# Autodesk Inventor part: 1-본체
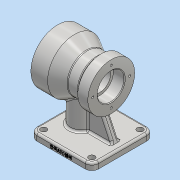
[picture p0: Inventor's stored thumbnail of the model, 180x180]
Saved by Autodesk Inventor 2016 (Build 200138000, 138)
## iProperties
Created: 2019-01
Part Number: 1-본체
Material: 알루미늄 6061
Document SubType Name: Modeling
Designer: Administrator
Density: 2.7 g/cm^3
Appearance: 알루미늄 - 평지
Mass: 904.622 g
Surface Area: 607.619 cm^2
Volume: 335.045 cm^3
Author: Administrator
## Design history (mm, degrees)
sketch "스케치2"
  geometry: L1 (0, 0)-(0, 40); L2 (0, 40)-(-25, 40); L3 (-25, 40)-(-44.053, 29); L4 (-44.053, 29)-(-59.965, 29); L5 (-59.965, 29)-(-65, 35); L6 (-65, 35)-(-80, 35); L7 (-80, 35)-(-80, 0); L8 (-80, 0)-(0, 0); L9 (0, 26)-(-20, 26); L10 (-20, 26)-(-20, 0); L11 (-80, 0)-(-63, 0); L12 (-63, 0)-(-63, 20); L13 (-63, 20)-(-80, 20); L14 (-80, 20)-(-80, 0); L15 (-20, 16)-(-63, 16); 1 further point
  constraints: 30 end point, 6 perpendicular, 4 parallel, 4 point on line, 2 horizontal, 1 coincident, 1 vertical
  dimensions: "d0" = 70 diameter of L6 L8; "d1" = 58 diameter of L4 L8; "d2" = 80 diameter of L2 L8; "d3" = 25 distance of L1.end L2.end; "d4" = 80 distance between parallel lines of L7 L1; "d5" = 15 distance of L5.end L6.end; "d6" = 20 distance between parallel lines of L10 L1; "d7" = 52 diameter of L9 L8; "d9" = 17 distance of L12.end L13.end; "d10" = 40 diameter of L13 L8; "d11" = 32 diameter of L15 L8; "d51" = 30 deg angle of L4 L3; "d52" = 50 deg angle of L5 L4
revolve "회전1" sketch "스케치2" stored, may be unused: angle "d12" = 90 deg
node "작업 평면1"
sketch "스케치3"
  geometry: L1 (5, -46)-(97, -46); L2 (97, -46)-(97, 46); L3 (97, 46)-(5, 46); L4 (5, 46)-(5, -46); 1 further point
  constraints: 8 end point, 2 parallel, 1 horizontal, 1 perpendicular
  dimensions: "d14" = 5 distance from line of L4 point (0, 0); "d15" = 92 distance of L2.end L3.end; "d16" = 92 distance of L3.end L1.start; "d17" = 46 distance from line of L1 point (0, 0) (= 0.5 x d16)
extrude "돌출1" join sketch "스케치3" distance "d18" = 10; taper "d19" = 0 deg
sketch "스케치4"
  geometry: L1 (5, 46)-(5, -46) reference; C1 r 16 at (35, 0); 1 further point
  constraints: 1 centre point
  dimensions: "d20" = 32 diameter of C1; "d21" = 30 distance from line of C1.centre L1
extrude "돌출2" join sketch "스케치4" distance "d23" = 50; taper "d24" = 0 deg
sketch "스케치5"
  geometry: L1 (-5, -70)-(-97, -70) reference; L2 (-87, -70)-(-66.302, -25.614); L3 (-97, -80)-(-97, -70) reference; L4 (-45.951, -25.614)-(-66.302, -25.614); L5 (-97, -70)-(-5, -70) reference; L6 (-45.951, -70)-(-45.951, -25.614); 5 further points
  constraints: 6 end point, 2 point on line, 1 horizontal, 1 vertical
  dimensions: "d25" = 10 distance from line of L2.start L3; "d26" = 25 deg angle of L2 L3
extrude "돌출3" join sketch "스케치5" stored distance "d27" = 10; taper "d28" = 0 deg
sketch "스케치6" dims "d29" = 55
  geometry: 3 further points
  constraints: 1 coincident, 1 horizontal alignment, 2 other
hole "구멍1" sketch "스케치6" at (-27.5, 0) diameter "d30" = 3.242; stored, may be unused: countersink angle "d34" = 90 deg, drill point angle "d36" = 118 deg; dims "d31" = 9, "d32" = 4, "d33" = 2, "d35" = 11
sketch "스케치7" dims "d40" = 66
  geometry: 3 further points
  constraints: 1 coincident, 1 horizontal alignment, 2 other
hole "구멍2" sketch "스케치7" at (33, 0) diameter "d41" = 3.242; stored, may be unused: countersink angle "d45" = 90 deg, drill point angle "d47" = 118 deg; dims "d42" = 9, "d43" = 4, "d44" = 2, "d46" = 11
sketch "스케치8"
  geometry: L1 (0, 0)-(0, 10) reference; L2 (0, 0)-(92, 0) reference; 2 further points
  constraints: 1 other
  dimensions: "d53" = 46 distance from line of point (46, 4) L1; "d54" = 4 distance from line of point (46, 4) L2
feature "엠보싱1" sketch "스케치8" dims "d0" = 70, "d1" = 58, "d2" = 80, "d3" = 25, "d4" = 80, "d5" = 15, "d6" = 20, "d7" = 52, "d9" = 17, "d10" = 40, "d11" = 32, "d14" = 5, "d15" = 92, "d16" = 92, "d17" = 46 (= 0.5 x d16), "d51" = 30 deg, "d52" = 50 deg, "d55" = 0.5, "d56" = 0
sketch "스케치9"
  geometry: L1 (15, -36)-(87, -36); L2 (87, -36)-(87, 36); L3 (87, 36)-(15, 36); L4 (15, 36)-(15, -36); L5 (5, 46)-(5, -46) reference; L6 (97, -46)-(97, 46) reference; L7 (97, 46)-(5, 46) reference; L8 (5, -46)-(97, -46) reference; 5 further points
  constraints: 8 end point, 4 coincident, 2 parallel, 1 horizontal, 1 perpendicular
  dimensions: "d57" = 10 distance between parallel lines of L5 L4; "d58" = 10 distance between parallel lines of L6 L2; "d59" = 10 distance between parallel lines of L7 L3; "d60" = 10 distance between parallel lines of L8 L1
hole "구멍3" sketch "스케치9" at (15, 36), (87, 36), (87, -36), (15, -36) diameter "d61" = 9; stored, may be unused: countersink angle "d65" = 90 deg, drill point angle "d67" = 118 deg; dims "d62" = 9, "d63" = 4, "d64" = 2, "d66" = 11
fillet "모깎기1" dims "d68" = 10
fillet "모깎기2" dims "d69" = 3
chamfer "모따기1" distance "d71" = 1; stored, may be unused: second distance "d72" = 2, angle "d73" = 45 deg
fillet "모깎기4" dims "d76" = 3
fillet "모깎기5" dims "d77" = 3
fillet "모깎기6" dims "d78" = 3
fillet "모깎기8" dims "d80" = 3
fillet "모깎기10" dims "d82" = 3
fillet "모깎기11" dims "d83" = 3
fillet "모깎기12" dims "d84" = 3
fillet "모깎기13" dims "d85" = 3
fillet "모깎기14" dims "d86" = 3
fillet "모깎기15" dims "d87" = 3
fillet "모깎기16" dims "d88" = 3
node "솔리드1"
pattern_circular "원형 패턴1" dims angle "d38" = 360 deg
pattern_circular "원형 패턴2" dims angle "d49" = 360 deg
